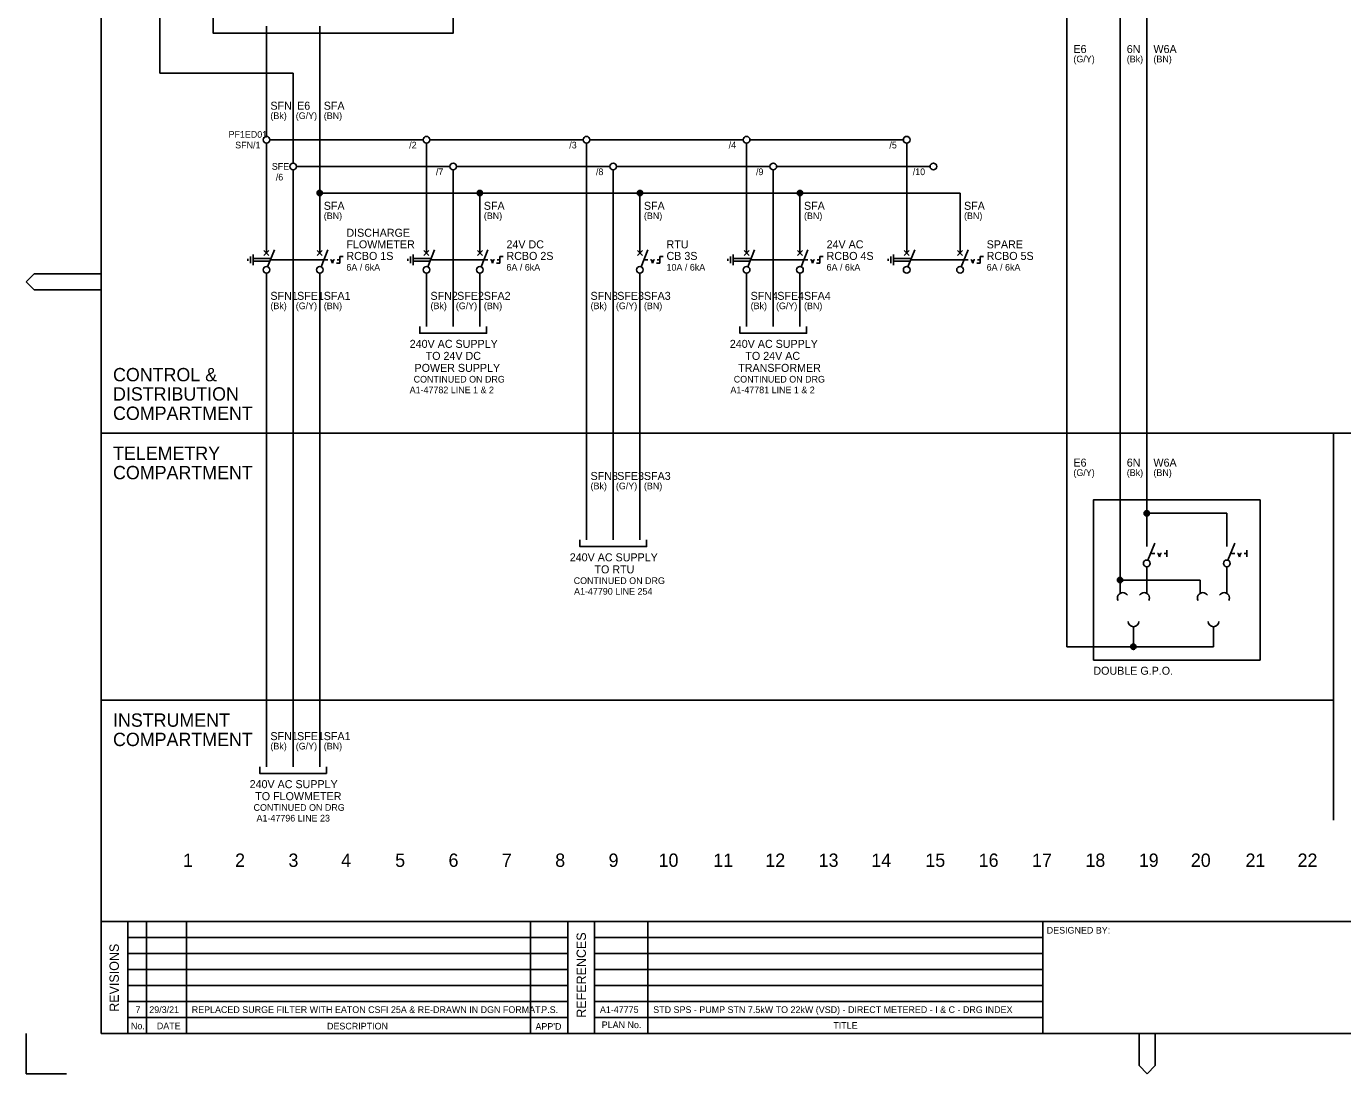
# Model space of a CAD drawing. Extents: x 0 to 841, y 0 to 594.
# Drawn here: x 0 to 493.4, y 0 to 392.5 of the extents above; entities that cross this region are included whole.
import ezdxf

# ---------------------------------------------------------------- set-up
doc = ezdxf.new("R2010")
doc.units = 0
for name, color, linetype in [('A1BORDER', 7, 'Continuous'), ('Level 1', 7, 'Continuous'), ('Level 10', 7, 'Continuous')]:
    doc.layers.add(name, color=color, linetype=linetype)

msp = doc.modelspace()

# ---------------------------------------------------------------- linework, layer by layer
at = {"layer": 'A1BORDER'}
for p, q in [((28, 581), (28, 15)), ((3, 299.76), (0, 296.76)), ((3, 293.76), (0, 296.76)), ((28, 299.76), (3, 299.76)), ((28, 293.76), (3, 293.76)), ((28, 57), (829, 57)), ((38, 15), (38, 57)), ((45, 15), (45, 57)), ((60, 15), (60, 57)), ((189, 15), (189, 57)), ((203, 15), (203, 57)), ((213, 15), (213, 57)), ((233, 15), (233, 57)), ((381, 15), (381, 57)), ((203, 51), (38, 51)), ((213, 51), (381, 51)), ((203, 45), (38, 45)), ((213, 45), (381, 45)), ((203, 39), (38, 39)), ((213, 39), (381, 39)), ((203, 33), (38, 33)), ((213, 33), (381, 33)), ((38, 27), (203, 27)), ((213, 27), (381, 27)), ((203, 21), (38, 21)), ((213, 21), (381, 21)), ((0, 0), (0, 15)), ((829, 15), (28, 15)), ((417.19, 15), (417.19, 3)), ((423.19, 15), (423.19, 3)), ((417.19, 3), (420.19, 0)), ((423.19, 3), (420.19, 0)), ((0, 0), (15, 0))]:
    msp.add_line(p, q, dxfattribs=at)
at = {"layer": 'Level 1'}
for p, q in [((50, 465), (50, 375)), ((419.98, 200), (419.98, 418.75)), ((410, 408.75), (410, 180)), ((390, 160), (390, 398.75)), ((90, 392.5), (90, 392.5)), ((90, 392.5), (90, 351.25)), ((110, 392.5), (110, 392.5)), ((110, 392.5), (110, 310)), ((50, 375), (100, 375)), ((100, 375), (100, 341.25)), ((90, 351.25), (90, 351.25)), ((150, 351.25), (150, 351.25)), ((210, 351.25), (210, 351.25)), ((270, 351.25), (270, 351.25)), ((330, 351.25), (330, 351.25)), ((90, 348.75), (90, 310)), ((90, 348.75), (90, 348.75)), ((91.25, 350), (148.75, 350)), ((150, 348.75), (150, 310)), ((150, 348.75), (150, 348.75)), ((151.25, 350), (208.75, 350)), ((210, 348.75), (210, 200)), ((210, 348.75), (210, 348.75)), ((211.25, 350), (268.75, 350)), ((270, 348.75), (270, 310)), ((270, 348.75), (270, 348.75)), ((271.25, 350), (328.75, 350)), ((330, 348.75), (330, 348.75)), ((330, 348.75), (330, 310)), ((100, 341.25), (100, 341.25)), ((160, 341.25), (160, 341.25)), ((220, 341.25), (220, 341.25)), ((280, 341.25), (280, 341.25)), ((340, 341.25), (340, 341.25)), ((100, 338.75), (100, 115)), ((100, 338.75), (100, 338.75)), ((101.25, 340), (158.75, 340)), ((160, 338.75), (160, 338.75)), ((160, 338.75), (160, 280)), ((161.25, 340), (218.75, 340)), ((220, 338.75), (220, 200)), ((220, 338.75), (220, 338.75)), ((221.25, 340), (278.75, 340)), ((280, 338.75), (280, 338.75)), ((280, 338.75), (280, 280)), ((281.25, 340), (338.75, 340)), ((340, 338.75), (340, 338.75)), ((350, 330), (110, 330)), ((170, 330), (170, 310)), ((230, 330), (230, 310)), ((290, 330), (290, 310)), ((350, 330), (350, 310)), ((89.06, 308.44), (90.94, 306.56)), ((90.94, 308.44), (89.06, 306.56)), ((90, 307.5), (90, 310)), ((90.46, 302.41), (93, 308.75)), ((109.06, 308.44), (110.94, 306.56)), ((110.94, 308.44), (109.06, 306.56)), ((110, 307.5), (110, 310)), ((110.46, 302.41), (113, 308.75)), ((149.06, 308.44), (150.94, 306.56)), ((150.94, 308.44), (149.06, 306.56)), ((150, 307.5), (150, 310)), ((150.46, 302.41), (153, 308.75)), ((169.06, 308.44), (170.94, 306.56)), ((170.94, 308.44), (169.06, 306.56)), ((170, 307.5), (170, 310)), ((170.46, 302.41), (173, 308.75)), ((229.06, 308.44), (230.94, 306.56)), ((230.94, 308.44), (229.06, 306.56)), ((230, 307.5), (230, 310)), ((230.46, 302.41), (233, 308.75)), ((269.06, 308.44), (270.94, 306.56)), ((270.94, 308.44), (269.06, 306.56)), ((270, 307.5), (270, 310)), ((270.46, 302.41), (273, 308.75)), ((289.06, 308.44), (290.94, 306.56)), ((290.94, 308.44), (289.06, 306.56)), ((290, 307.5), (290, 310)), ((290.46, 302.41), (293, 308.75)), ((329.06, 308.44), (330.94, 306.56)), ((330.94, 308.44), (329.06, 306.56)), ((330, 307.5), (330, 310)), ((330.46, 302.41), (333, 308.75)), ((349.06, 308.44), (350.94, 306.56)), ((350.94, 308.44), (349.06, 306.56)), ((350, 307.5), (350, 310)), ((350.46, 302.41), (353, 308.75)), ((85, 305.5), (91.7, 305.5)), ((85, 304.5), (91.3, 304.5)), ((91.5, 305), (111.5, 305)), ((145, 305.5), (151.7, 305.5)), ((145, 304.5), (151.3, 304.5)), ((151.5, 305), (171.5, 305)), ((265, 305.5), (271.7, 305.5)), ((265, 304.5), (271.3, 304.5)), ((271.5, 305), (291.5, 305)), ((325, 305.5), (331.7, 305.5)), ((325, 304.5), (331.3, 304.5)), ((331.5, 305), (351.5, 305)), ((90, 300), (90, 115)), ((110, 300), (110, 115)), ((150, 300), (150, 280)), ((170, 300), (170, 280)), ((230, 300), (230, 200)), ((270, 300), (270, 280)), ((290, 300), (290, 280)), ((28, 240), (829, 240)), ((490, 240), (490, 95)), ((449.98, 210), (419.98, 210)), ((449.98, 200), (449.98, 210)), ((419.98, 197.5), (419.98, 200)), ((419.98, 200), (419.98, 200)), ((420.44, 192.41), (422.98, 198.75)), ((449.98, 197.5), (449.98, 200)), ((449.98, 200), (449.98, 200)), ((450.44, 192.41), (452.98, 198.75)), ((421.48, 195), (422.98, 195)), ((423.98, 195), (424.31, 195)), ((424.73, 193.75), (424.31, 195)), ((424.73, 193.75), (425.15, 195)), ((425.48, 195), (425.15, 195)), ((426.48, 195), (427.48, 195)), ((427.48, 193.75), (427.48, 196.25)), ((451.48, 195), (452.98, 195)), ((453.98, 195), (454.31, 195)), ((454.73, 193.75), (454.31, 195)), ((454.73, 193.75), (455.15, 195)), ((455.48, 195), (455.15, 195)), ((456.48, 195), (457.48, 195)), ((457.48, 193.75), (457.48, 196.25)), ((419.98, 190), (419.98, 190)), ((419.98, 190), (419.98, 180)), ((449.98, 190), (449.98, 190)), ((449.98, 190), (449.98, 180)), ((410, 185), (410, 180)), ((440, 185), (410, 185)), ((440, 185), (440, 180)), ((415, 167.5), (415, 160)), ((445, 167.5), (445, 160)), ((445, 160), (390, 160)), ((28, 140), (490, 140))]:
    msp.add_line(p, q, dxfattribs=at)
for points in [[(70, 450), (160, 450), (160, 390), (70, 390)], [(400, 155), (462.5, 155), (462.5, 215), (400, 215)]]:
    msp.add_lwpolyline(points, close=True, dxfattribs=at)
for points in [[(147.5, 280), (147.5, 277.5), (172.5, 277.5), (172.5, 280)], [(267.5, 280), (267.5, 277.5), (292.5, 277.5), (292.5, 280)], [(207.5, 200), (207.5, 197.5), (232.5, 197.5), (232.5, 200)], [(87.5, 115), (87.5, 112.5), (112.5, 112.5), (112.5, 115)]]:
    msp.add_lwpolyline(points, dxfattribs=at)
for centre in [(90, 301.25), (110, 301.25), (150, 301.25), (170, 301.25), (230, 301.25), (270, 301.25), (290, 301.25), (330, 301.25), (350, 301.25), (419.98, 191.25), (449.98, 191.25)]:
    msp.add_circle(centre, 1.25, dxfattribs=at)
at = {"layer": 'Level 10'}
for p, q in [((109.2, 330.6), (110.8, 330.6)), ((109.56, 330.9), (110.44, 330.9)), ((110, 331), (110, 331)), ((169.2, 330.6), (170.8, 330.6)), ((169.56, 330.9), (170.44, 330.9)), ((170, 331), (170, 331)), ((229.2, 330.6), (230.8, 330.6)), ((229.56, 330.9), (230.44, 330.9)), ((230, 331), (230, 331)), ((289.2, 330.6), (290.8, 330.6)), ((289.56, 330.9), (290.44, 330.9)), ((290, 331), (290, 331)), ((109, 330), (110.99, 330)), ((109.05, 330.3), (110.95, 330.3)), ((109.05, 329.7), (110.95, 329.7)), ((109.2, 329.4), (110.8, 329.4)), ((109.56, 329.1), (110.44, 329.1)), ((169, 330), (170.99, 330)), ((169.05, 330.3), (170.95, 330.3)), ((169.05, 329.7), (170.95, 329.7)), ((169.2, 329.4), (170.8, 329.4)), ((169.56, 329.1), (170.44, 329.1)), ((229, 330), (230.99, 330)), ((229.05, 330.3), (230.95, 330.3)), ((229.05, 329.7), (230.95, 329.7)), ((229.2, 329.4), (230.8, 329.4)), ((229.56, 329.1), (230.44, 329.1)), ((289, 330), (290.99, 330)), ((289.05, 330.3), (290.95, 330.3)), ((289.05, 329.7), (290.95, 329.7)), ((289.2, 329.4), (290.8, 329.4)), ((289.56, 329.1), (290.44, 329.1)), ((84, 306.2), (84, 303.8)), ((85, 307), (85, 303)), ((117.5, 303.75), (117.5, 306.25)), ((117.5, 306.25), (118.75, 306.25)), ((144, 306.2), (144, 303.8)), ((145, 307), (145, 303)), ((177.5, 303.75), (177.5, 306.25)), ((177.5, 306.25), (178.75, 306.25)), ((237.5, 303.75), (237.5, 306.25)), ((237.5, 306.25), (238.75, 306.25)), ((264, 306.2), (264, 303.8)), ((265, 307), (265, 303)), ((297.5, 303.75), (297.5, 306.25)), ((297.5, 306.25), (298.75, 306.25)), ((324, 306.2), (324, 303.8)), ((325, 307), (325, 303)), ((357.5, 303.75), (357.5, 306.25)), ((357.5, 306.25), (358.75, 306.25)), ((83, 305.4), (83, 304.6)), ((111.5, 305), (113, 305)), ((114, 305), (114.33, 305)), ((114.75, 303.75), (114.33, 305)), ((114.75, 303.75), (115.17, 305)), ((115.5, 305), (115.17, 305)), ((116.25, 303.75), (117.5, 303.75)), ((116.5, 305), (117.5, 305)), ((143, 305.4), (143, 304.6)), ((171.5, 305), (173, 305)), ((174, 305), (174.33, 305)), ((174.75, 303.75), (174.33, 305)), ((174.75, 303.75), (175.17, 305)), ((175.5, 305), (175.17, 305)), ((176.25, 303.75), (177.5, 303.75)), ((176.5, 305), (177.5, 305)), ((231.5, 305), (233, 305)), ((234, 305), (234.33, 305)), ((234.75, 303.75), (234.33, 305)), ((234.75, 303.75), (235.17, 305)), ((235.5, 305), (235.17, 305)), ((236.25, 303.75), (237.5, 303.75)), ((236.5, 305), (237.5, 305)), ((263, 305.4), (263, 304.6)), ((291.5, 305), (293, 305)), ((294, 305), (294.33, 305)), ((294.75, 303.75), (294.33, 305)), ((294.75, 303.75), (295.17, 305)), ((295.5, 305), (295.17, 305)), ((296.25, 303.75), (297.5, 303.75)), ((296.5, 305), (297.5, 305)), ((323, 305.4), (323, 304.6)), ((351.5, 305), (353, 305)), ((354, 305), (354.33, 305)), ((354.75, 303.75), (354.33, 305)), ((354.75, 303.75), (355.17, 305)), ((355.5, 305), (355.17, 305)), ((356.25, 303.75), (357.5, 303.75)), ((356.5, 305), (357.5, 305)), ((419, 209.89), (420.6, 210.81)), ((419.04, 210.25), (420.26, 210.96)), ((419.09, 209.59), (420.81, 210.58)), ((419.25, 209.34), (420.95, 210.32)), ((419.5, 210.87), (419.5, 210.87)), ((419.5, 209.13), (421, 210)), ((419.88, 209.01), (420.92, 209.61)), ((409, 184.89), (410.6, 185.81)), ((409.04, 185.25), (410.26, 185.96)), ((409.09, 184.59), (410.81, 185.58)), ((409.25, 184.34), (410.95, 185.32)), ((409.5, 185.87), (409.5, 185.87)), ((409.5, 184.13), (411, 185)), ((409.88, 184.01), (410.92, 184.61)), ((414, 159.89), (415.6, 160.81)), ((414.04, 160.25), (415.26, 160.96)), ((414.09, 159.59), (415.81, 160.58)), ((414.25, 159.34), (415.95, 160.32)), ((414.5, 160.87), (414.5, 160.87)), ((414.5, 159.13), (416, 160)), ((414.88, 159.01), (415.92, 159.61))]:
    msp.add_line(p, q, dxfattribs=at)
for centre, radius in [((90, 350), 1.25), ((150, 350), 1.25), ((210, 350), 1.25), ((270, 350), 1.25), ((330, 350), 1.25), ((100, 340), 1.25), ((160, 340), 1.25), ((220, 340), 1.25), ((280, 340), 1.25), ((340, 340), 1.25), ((110, 330), 1), ((170, 330), 1), ((230, 330), 1), ((290, 330), 1), ((420, 210), 1), ((410, 185), 1), ((415, 160), 1)]:
    msp.add_circle(centre, radius, dxfattribs=at)
for centre, start, end in [((411, 178.27), 30, 210), ((419, 178.27), 330, 150), ((441, 178.27), 30, 210), ((449, 178.27), 330, 150), ((415, 169.5), 180, 0), ((445, 169.5), 180, 0)]:
    msp.add_arc(centre, 2, start, end, dxfattribs=at)

# ---------------------------------------------------------------- texts
at = {"layer": 'A1BORDER'}
for s, p in [('DESIGNED BY:', (382.5, 52.5)), ('No.', (39.21, 16.65)), ('DATE', (48.92, 16.65)), ('DESCRIPTION', (112.71, 16.57)), ("APP'D", (190.85, 16.44)), ('PLAN No.', (215.69, 17.06)), ('TITLE', (302.5, 16.81))]:
    msp.add_text(s, height=2.5, dxfattribs=at).set_placement(p)
for s, p in [('REFERENCES', (209.76, 20.96)), ('REVISIONS', (34.68, 23.2))]:
    msp.add_text(s, height=3.5, rotation=90, dxfattribs=at).set_placement(p)
at = {"layer": 'Level 1'}
for s, height, p in [('E6', 3, (392.5, 382.5)), ('6N', 3, (412.5, 382.5)), ('W6A', 3, (422.5, 382.5)), ('(G/Y)', 2.5, (392.5, 379)), ('(Bk)', 2.5, (412.5, 379)), ('(BN)', 2.5, (422.5, 379)), ('SFN', 3, (91.5, 361.25)), ('SFN', 3, (91.5, 361.25)), ('(Bk)', 2.5, (91.5, 357.75)), ('(Bk)', 2.5, (91.5, 357.75)), ('(G/Y)', 2.5, (101, 357.75)), ('E6', 3, (101.5, 361.25)), ('SFA', 3, (111.5, 361.25)), ('SFA', 3, (111.5, 361.25)), ('(BN)', 2.5, (111.5, 357.75)), ('(BN)', 2.5, (111.5, 357.75)), ('PF1ED01', 2.5, (75.8, 350.74)), ('SFN/1', 2.5, (78.29, 346.74)), ('/2', 2.5, (143.52, 346.74)), ('/3', 2.5, (203.52, 346.74)), ('/4', 2.5, (263.27, 346.74)), ('/5', 2.5, (323.52, 346.74)), ('SFE', 2.5, (92.02, 338.74)), ('/6', 2.5, (93.52, 334.74)), ('/7', 2.5, (153.52, 336.74)), ('/8', 2.5, (213.52, 336.74)), ('/9', 2.5, (273.52, 336.74)), ('/10', 2.5, (332.27, 336.74)), ('SFA', 3, (111.5, 323.75)), ('SFA', 3, (171.5, 323.75)), ('SFA', 3, (231.5, 323.75)), ('SFA', 3, (291.5, 323.75)), ('SFA', 3, (351.5, 323.75)), ('(BN)', 2.5, (111.5, 320.25)), ('(BN)', 2.5, (171.5, 320.25)), ('(BN)', 2.5, (231.5, 320.25)), ('(BN)', 2.5, (291.5, 320.25)), ('(BN)', 2.5, (351.5, 320.25)), ('DISCHARGE', 3, (119.98, 313.64)), ('FLOWMETER', 3, (119.98, 309.3)), ('24V DC', 3, (179.98, 309.3)), ('RTU', 3, (239.98, 309.3)), ('24V AC', 3, (299.98, 309.3)), ('SPARE', 3, (359.98, 309.3)), ('RCBO 1S', 3, (119.98, 304.96)), ('RCBO 2S', 3, (179.98, 304.96)), ('CB 3S', 3, (239.98, 304.96)), ('RCBO 4S', 3, (299.98, 304.96)), ('RCBO 5S', 3, (359.98, 304.96)), ('6A / 6kA', 2.5, (119.98, 300.96)), ('6A / 6kA', 2.5, (179.98, 300.96)), ('10A / 6kA', 2.5, (239.98, 300.96)), ('6A / 6kA', 2.5, (299.98, 300.96)), ('6A / 6kA', 2.5, (359.98, 300.96)), ('SFN1', 3, (91.5, 290)), ('SFE1', 3, (101.5, 290)), ('SFA1', 3, (111.5, 290)), ('SFN2', 3, (151.5, 290)), ('SFE2', 3, (161.5, 290)), ('SFA2', 3, (171.5, 290)), ('SFN3', 3, (211.5, 290)), ('SFE3', 3, (221.5, 290)), ('SFA3', 3, (231.5, 290)), ('SFN4', 3, (271.5, 290)), ('SFE4', 3, (281.5, 290)), ('SFA4', 3, (291.5, 290)), ('(Bk)', 2.5, (91.5, 286.5)), ('(G/Y)', 2.5, (101, 286.5)), ('(BN)', 2.5, (111.5, 286.5)), ('(Bk)', 2.5, (151.5, 286.5)), ('(G/Y)', 2.5, (161, 286.5)), ('(BN)', 2.5, (171.5, 286.5)), ('(Bk)', 2.5, (211.5, 286.5)), ('(G/Y)', 2.5, (221, 286.5)), ('(BN)', 2.5, (231.5, 286.5)), ('(Bk)', 2.5, (271.5, 286.5)), ('(G/Y)', 2.5, (281, 286.5)), ('(BN)', 2.5, (291.5, 286.5)), ('240V AC SUPPLY', 3, (143.71, 272)), ('240V AC SUPPLY', 3, (263.71, 272)), ('TO 24V DC', 3, (149.69, 267.5)), ('TO 24V AC', 3, (269.54, 267.5)), ('CONTROL &', 5, (32.5, 259.47)), ('CONTINUED ON DRG', 2.5, (145.18, 259)), ('POWER SUPPLY', 3, (145.51, 263)), ('CONTINUED ON DRG', 2.5, (265.18, 259)), ('TRANSFORMER', 3, (266.85, 263)), ('DISTRIBUTION', 5, (32.5, 252.24)), ('A1-47782 LINE 1 & 2', 2.5, (143.69, 255)), ('A1-47781 LINE 1 & 2', 2.5, (263.94, 255)), ('COMPARTMENT', 5, (32.5, 245)), ('TELEMETRY', 5, (32.5, 230)), ('COMPARTMENT', 5, (32.5, 222.76)), ('E6', 3, (392.5, 227.5)), ('6N', 3, (412.5, 227.5)), ('W6A', 3, (422.5, 227.5)), ('SFN3', 3, (211.5, 222.5)), ('SFE3', 3, (221.5, 222.5)), ('SFA3', 3, (231.5, 222.5)), ('(G/Y)', 2.5, (392.5, 224)), ('(Bk)', 2.5, (412.5, 224)), ('(BN)', 2.5, (422.5, 224)), ('(Bk)', 2.5, (211.5, 219)), ('(G/Y)', 2.5, (221, 219)), ('(BN)', 2.5, (231.5, 219)), ('240V AC SUPPLY', 3, (203.71, 192)), ('TO RTU', 3, (212.98, 187.5)), ('CONTINUED ON DRG', 2.5, (205.18, 183.5)), ('A1-47790 LINE 254', 2.5, (205.31, 179.5)), ('DOUBLE G.P.O.', 3, (399.98, 149.5)), ('INSTRUMENT', 5, (32.5, 130)), ('COMPARTMENT', 5, (32.5, 122.76)), ('SFN1', 3, (91.5, 125)), ('(Bk)', 2.5, (91.5, 121.5)), ('(G/Y)', 2.5, (101, 121.5)), ('SFE1', 3, (101.5, 125)), ('SFA1', 3, (111.5, 125)), ('(BN)', 2.5, (111.5, 121.5)), ('240V AC SUPPLY', 3, (83.71, 107)), ('TO FLOWMETER', 3, (85.81, 102.5)), ('CONTINUED ON DRG', 2.5, (85.18, 98.5)), ('A1-47796 LINE 23', 2.5, (86.3, 94.5)), ('1', 5, (58.76, 77.5)), ('2', 5, (78.26, 77.5)), ('3', 5, (98.26, 77.5)), ('4', 5, (118.01, 77.5)), ('5', 5, (138.26, 77.5)), ('6', 5, (158.26, 77.5)), ('7', 5, (178.26, 77.5)), ('8', 5, (198.26, 77.5)), ('9', 5, (218.26, 77.5)), ('10', 5, (237.01, 77.5)), ('11', 5, (257.51, 77.5)), ('12', 5, (277.01, 77.5)), ('13', 5, (297.01, 77.5)), ('14', 5, (316.76, 77.5)), ('15', 5, (337.01, 77.5)), ('16', 5, (357.01, 77.5)), ('17', 5, (377.01, 77.5)), ('18', 5, (397.01, 77.5)), ('19', 5, (417.01, 77.5)), ('20', 5, (436.52, 77.5)), ('21', 5, (457.01, 77.5)), ('22', 5, (476.52, 77.5)), ('7', 2.5, (40.94, 22.75)), ('29/3/21', 2.5, (46.09, 22.75)), ('REPLACED SURGE FILTER WITH EATON CSFI 25A & RE-DRAWN IN DGN FORMAT.', 2.5, (62, 22.75)), ('P.S.', 2.5, (193.02, 22.75)), ('A1-47775', 2.5, (215, 22.75)), ('STD SPS - PUMP STN 7.5kW TO 22kW (VSD) - DIRECT METERED - I & C - DRG INDEX', 2.5, (235, 22.75))]:
    msp.add_text(s, height=height, dxfattribs=at).set_placement(p)

doc.saveas('drawing.dxf')
